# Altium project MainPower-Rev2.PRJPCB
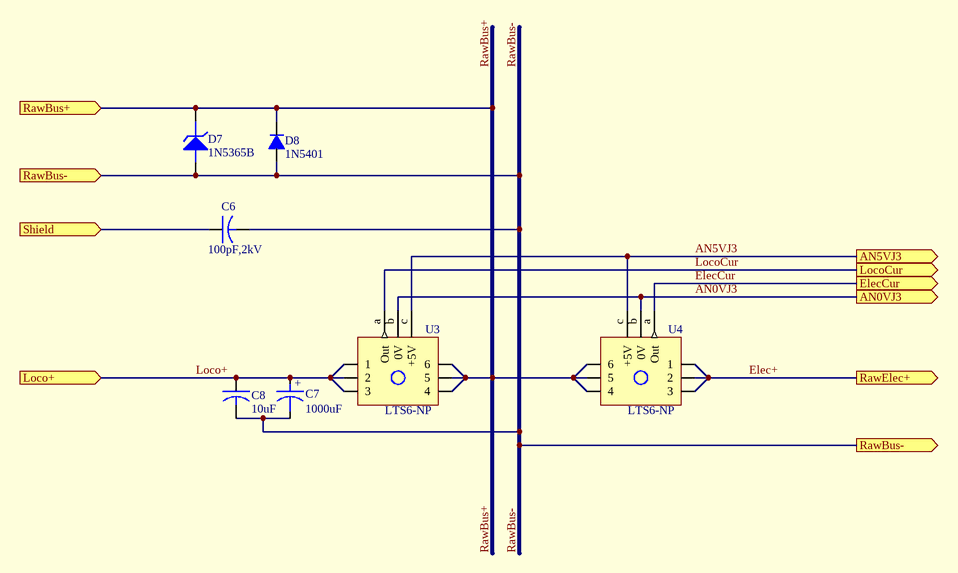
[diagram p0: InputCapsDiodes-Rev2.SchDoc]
8 sheets, 82 parts. Net scope: flat (ports and power ports of the same name join across sheets).
Board file: MainPower-Rev2.PcbDoc
Sheets:
  InputCapsDiodes-Rev2.SchDoc
  Iso5V-25W-MVC-Rev2.SchDoc
  Iso12V-30W-MVC-Rev2.SchDoc
  Iso9V-1W-Parosci-Rev2.SchDoc
  NonIso3.3V-5W-GPS-Rev2.SchDoc
  NonIso5V-13W-Iridium-Rev2.SchDoc
  BattBacked-Rev2.SCHDOC
  Watchdog-Rev2.SchDoc

## Sheet InputCapsDiodes-Rev2.SchDoc
size Tabloid; Organization: Monterey Bay Aquarium Research Institute; Address1: 7700 Sandholdt Rd; Address2: Moss Landing, CA 95039-9644; CompanyName: MBARI

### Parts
C6  100pF,2kV  [ECK]
C7  1000uF  [RAD0.3L_0.63D]
C8  10uF  [CAPSTICK-CS4-5]
D7  1N5365B  [DO-201AD]
D8  1N5401  [DO-201AD]
U3  LTS6-NP  [LTS6-NP]
U4  LTS6-NP  [LTS6-NP]

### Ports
AN0VJ3 (out), AN5VJ3 (out), ElecCur (out), Loco+ (in), LocoCur (out), RawBus+ (in), RawBus- (in), RawBus- (out), RawElec+ (out), Shield (in)

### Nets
AN0VJ3: U3.b(0V) U4.b(0V) ; port AN0VJ3
AN5VJ3: U3.c(+5V) U4.c(+5V) ; port AN5VJ3
Elec+: U4.1 U4.2 U4.3 ; port RawElec+
ElecCur: U4.a(Out) ; port ElecCur
Loco+: C7.1 C8.1 U3.1 U3.2 U3.3 ; port Loco+
LocoCur: U3.a(Out) ; port LocoCur
RawBus+: D7.2(K) D8.2(A) U3.4 U3.5 U3.6 U4.4 U4.5 U4.6 ; port RawBus+
RawBus-: C6.2 C7.2 C8.2 D7.1(A) D8.1(K) ; port RawBus-
NetC6_1: C6.1 ; port Shield

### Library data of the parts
C6 = CAPACITOR: ManufPartNo: ECK-T3D101KB; Manufacturer: Panasonic; VendorPartNo: PCC2092CT-ND; Cost/ea: 0.99; Reference: T033, 764; Vendor: Digi-Key
C7 = CAPACITOR POL: Capacitor; ManufPartNo: EEU-FC1H102; Manufacturer: Panasonic; VendorPartNo: P10333-ND; Cost/ea: 1.485; Vendor: Digi-Key
C8 = CAPACITOR: ManufPartNo: 106K050CS4G; Manufacturer: ITW Paktron; VendorPartNo: AMP50V106-K10G; Cost/ea: 8.04; Vendor: Future
D7 = ZENER3: Zener Diode; ManufPartNo: 2EZ36D5; Manufacturer: Microsemi; VendorPartNo: 2EZ36D5MSCT-ND; Cost/ea: 0.75; Vendor: Digi-Key
D8 = DIODE_S: Diode; ManufPartNo: 1N5401-T; Manufacturer: Diodes Inc; VendorPartNo: 1N5401DICT-ND; Cost/ea: 0.41; Reference: T033, 578; Vendor: Digi-Key
U3 U4 = LTS6-NP: Current Transducer; Manufacturer: LEM; VendorPartNo: 398-1000-ND; Vendor: Digi-Key; Cost/ea: 19.20

## Sheet Iso5V-25W-MVC-Rev2.SchDoc
size Tabloid; Organization: Monterey Bay Aquarium Research Institute; Address1: 7700 Sandholdt Rd; Address2: Moss Landing, CA 95039-9644; CompanyName: MBARI
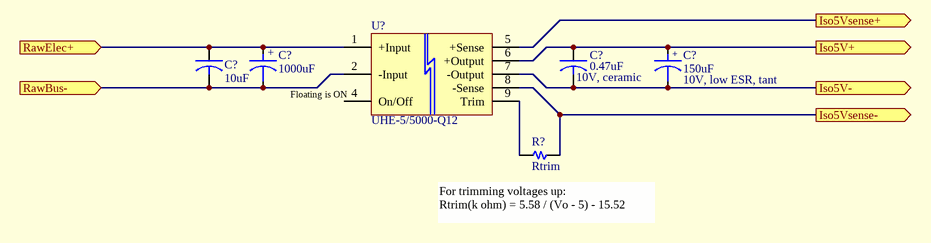
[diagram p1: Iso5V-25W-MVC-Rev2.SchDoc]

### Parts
C9  1000uF  [RAD0.3L_0.63D]
C10  10uF  [CAPSTICK-CS4-5]
C12  150uF  DescSheet: 10V, low ESR, tant  [7343pol]
C?  0.47uF  DescSheet: 10V, ceramic
R6  Rtrim  [AXIAL0.7]
U5  UHE-5/5000-Q12  [DATEL-UHE]

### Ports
Iso5V+ (out), Iso5V- (out), Iso5Vsense+ (out), Iso5Vsense- (out), RawBus- (in), RawElec+ (in)

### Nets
Elec+: C9.1 C10.1 U5.1(+Input) ; port RawElec+
RawBus-: C9.2 C10.2 U5.2(-Input) ; port RawBus-
NetC12_1: C12.1 C?.1 U5.6(+Output) ; port Iso5V+
NetC12_2: C12.2 C?.2 U5.7(-Output) ; port Iso5V-
NetR6_1: R6.1 U5.9(Trim)
NetR6_2: R6.2 U5.8(-Sense) ; port Iso5Vsense-
NetU5_5: U5.5(+Sense) ; port Iso5Vsense+

Not connected (* = marked no-connect by the designer): U5 4(On/Off)

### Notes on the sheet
- (near U5) Floating is ON
- (near R6) For trimming voltages up:
  Rtrim(k ohm) = 5.58 / (Vo - 5) - 15.52

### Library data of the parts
C9 = CAPACITOR POL: Capacitor
C10 C? = CAPACITOR
C12 = CAPACITOR POL: Tantalum Capacitor; ManufPartNo: EEJ-L1AD157R; Manufacturer: Panasonic; VendorPartNo: P11289CT-ND; Cost/ea: 1.884; Vendor: Digi-Key
R6 = RESISTOR
U5 = UHE: Datel UHE DC->DC Isolated Converter; Cost/ea: 61.90

## Sheet Iso12V-30W-MVC-Rev2.SchDoc
size Tabloid; Organization: Monterey Bay Aquarium Research Institute; Address1: 7700 Sandholdt Rd; Address2: Moss Landing, CA 95039-9644; CompanyName: MBARI
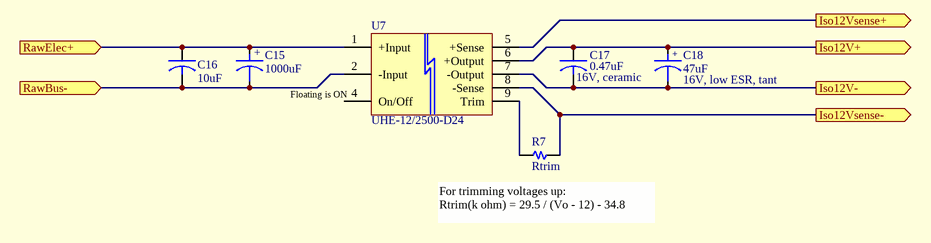
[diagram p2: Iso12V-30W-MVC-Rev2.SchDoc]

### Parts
C15  1000uF  [RAD0.3L_0.63D]
C16  10uF  [CAPSTICK-CS4-5]
C17  0.47uF  DescSheet: 16V, ceramic  [0805]
C18  47uF  DescSheet: 16V, low ESR, tant  [7343pol]
R7  Rtrim  [AXIAL0.7]
U7  UHE-12/2500-D24  [DATEL-UHE]

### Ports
Iso12V+ (out), Iso12V- (out), Iso12Vsense+ (out), Iso12Vsense- (out), RawBus- (in), RawElec+ (in)

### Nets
Elec+: C15.1 C16.1 U7.1(+Input) ; port RawElec+
RawBus-: C15.2 C16.2 U7.2(-Input) ; port RawBus-
NetC13_1: C17.1 C18.1 U7.6(+Output) ; port Iso12V+
NetC13_2: C17.2 C18.2 U7.7(-Output) ; port Iso12V-
NetR7_1: R7.1 U7.9(Trim)
NetR7_2: R7.2 U7.8(-Sense) ; port Iso12Vsense-
NetU7_5: U7.5(+Sense) ; port Iso12Vsense+

Not connected (* = marked no-connect by the designer): U7 4(On/Off)

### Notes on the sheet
- (near U7) Floating is ON
- (near R7) For trimming voltages up:
  Rtrim(k ohm) = 29.5 / (Vo - 12) - 34.8

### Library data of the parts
C15 = CAPACITOR POL: as C7 on sheet InputCapsDiodes-Rev2
C16 = CAPACITOR: as C8 on sheet InputCapsDiodes-Rev2
C17 = CAPACITOR: ManufPartNo: ECJ-2YB1C474K; Manufacturer: Panasonic; VendorPartNo: PCC1818CT-ND; Cost/ea: 0.245; Reference: T033, 771; Vendor: Digi-Key
C18 = CAPACITOR POL: Tantalum Capacitor; ManufPartNo: EEJ-L1CD476R; Manufacturer: Panasonic; VendorPartNo: P11291CT-ND; Cost/ea: 1.605; Vendor: Digi-Key
R7 = RESISTOR
U7 = UHE: Datel UHE DC->DC Isolated Converter; Cost/ea: 58.90

## Sheet Iso9V-1W-Parosci-Rev2.SchDoc
size Tabloid; Organization: Monterey Bay Aquarium Research Institute; Address1: 7700 Sandholdt Rd; Address2: Moss Landing, CA 95039-9644; CompanyName: MBARI
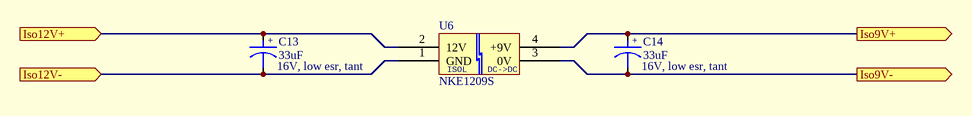
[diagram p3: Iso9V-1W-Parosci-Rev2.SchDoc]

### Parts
C13  33uF  DescSheet: 16V, low esr, tant  [6032pol]
C14  33uF  DescSheet: 16V, low esr, tant  [6032pol]
U6  NKE1209S  [NKEDCDC]

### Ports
Iso9V+ (out), Iso9V- (out), Iso12V+ (in), Iso12V- (in)

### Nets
NetC13_1: C13.1 U6.2(12V) ; port Iso12V+
NetC13_2: C13.2 U6.1(GND) ; port Iso12V-
NetC14_1: C14.1 U6.4(+9V) ; port Iso9V+
NetC14_2: C14.2 U6.3(0V) ; port Iso9V-

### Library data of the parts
C13 C14 = CAPACITOR POL: Capacitor; ManufPartNo: EEJ-L1CC336R; Manufacturer: Panasonic; VendorPartNo: P11290CT-ND; Cost/ea: 1.057; Vendor: Digi-Key
U6 = NKE1209S: DC->DC Isol Converter 12->9VDC; Manufacturer: C&D Technologies; VendorPartNo: 580-NKE1209S; Cost/ea: 8.33; Reference: Cat616, 1032; Vendor: Mouser

## Sheet NonIso3.3V-5W-GPS-Rev2.SchDoc
size Tabloid; Organization: Monterey Bay Aquarium Research Institute; Address1: 7700 Sandholdt Rd; Address2: Moss Landing, CA 95039-9644; CompanyName: MBARI
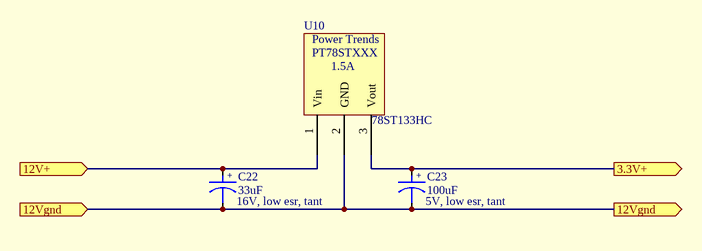
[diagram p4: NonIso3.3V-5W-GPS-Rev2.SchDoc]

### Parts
C22  33uF  DescSheet: 16V, low esr, tant  [6032pol]
C23  100uF  DescSheet: 5V, low esr, tant  [6032pol]
U10  78ST133HC  [PT78ST-HORIZ]

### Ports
3.3V+ (out), 12V+ (in), 12Vgnd (in), 12Vgnd (out)

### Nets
NetC22_1: C22.1 U10.1(Vin) ; port 12V+
NetC22_2: C22.2 C23.2 U10.2(GND) ; port 12Vgnd
NetC23_1: C23.1 U10.3(Vout) ; port 3.3V+

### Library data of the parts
C22 = CAPACITOR POL: Capacitor; ManufPartNo: EEJ-L1CC336R; Manufacturer: Panasonic; VendorPartNo: P11290CT-ND; Cost/ea: 1.057; Reference: T033, 718; Vendor: Digi-Key
C23 = CAPACITOR POL: Capacitor; ManufPartNo: EEJ-L0JC107R; Manufacturer: Panasonic; VendorPartNo: P11284CT-ND; Cost/ea: 1.196; Reference: T033, 718; Vendor: Digi-Key
U10 = PT78STXXX: Power Trends Switching Reg; Manufacturer: TI Power Trends; VendorPartNo: 78ST133HC-ND; Cost/ea: 15.38; Reference: T033, 1102; Vendor: Digi-Key

## Sheet NonIso5V-13W-Iridium-Rev2.SchDoc
size Tabloid; Organization: Monterey Bay Aquarium Research Institute; Address1: 7700 Sandholdt Rd; Address2: Moss Landing, CA 95039-9644; CompanyName: MBARI
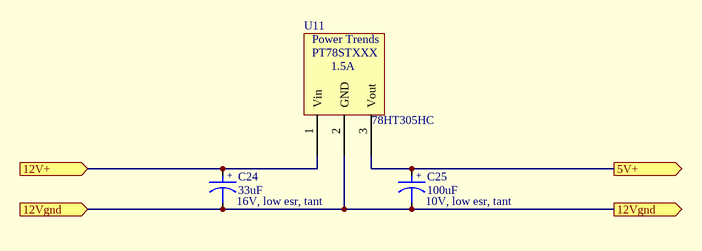
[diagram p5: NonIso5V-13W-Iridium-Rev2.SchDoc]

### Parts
C24  33uF  DescSheet: 16V, low esr, tant  [6032pol]
C25  100uF  DescSheet: 10V, low esr, tant  [7343pol]
U11  78HT305HC  [PT78ST-HORIZ]

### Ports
5V+ (out), 12V+ (in), 12Vgnd (in), 12Vgnd (out)

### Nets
NetC22_1: C24.1 U11.1(Vin) ; port 12V+
NetC22_2: C24.2 C25.2 U11.2(GND) ; port 12Vgnd
NetC25_1: C25.1 U11.3(Vout) ; port 5V+

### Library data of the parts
C24 = CAPACITOR POL: as C22 on sheet NonIso3.3V-5W-GPS-Rev2
C25 = CAPACITOR POL: Capacitor; ManufPartNo: EEJ-L1AD107R; Manufacturer: Panasonic; VendorPartNo: P11288CT-ND; Cost/ea: 1.688; Reference: T033, 718; Vendor: Digi-Key
U11 = PT78STXXX: Power Trends Switching Reg 5V, 3A; Manufacturer: TI Power Trends; VendorPartNo: 78HT305HC-ND; Cost/ea: 22.50; Reference: T033, 1103; Vendor: Digi-Key

## Sheet BattBacked-Rev2.SCHDOC
size Tabloid; Organization: Monterey Bay Aquarium Research Institute; Address1: 7700 Sandholdt Rd; Address2: Moss Landing, CA 95039-9644; CompanyName: MBARI
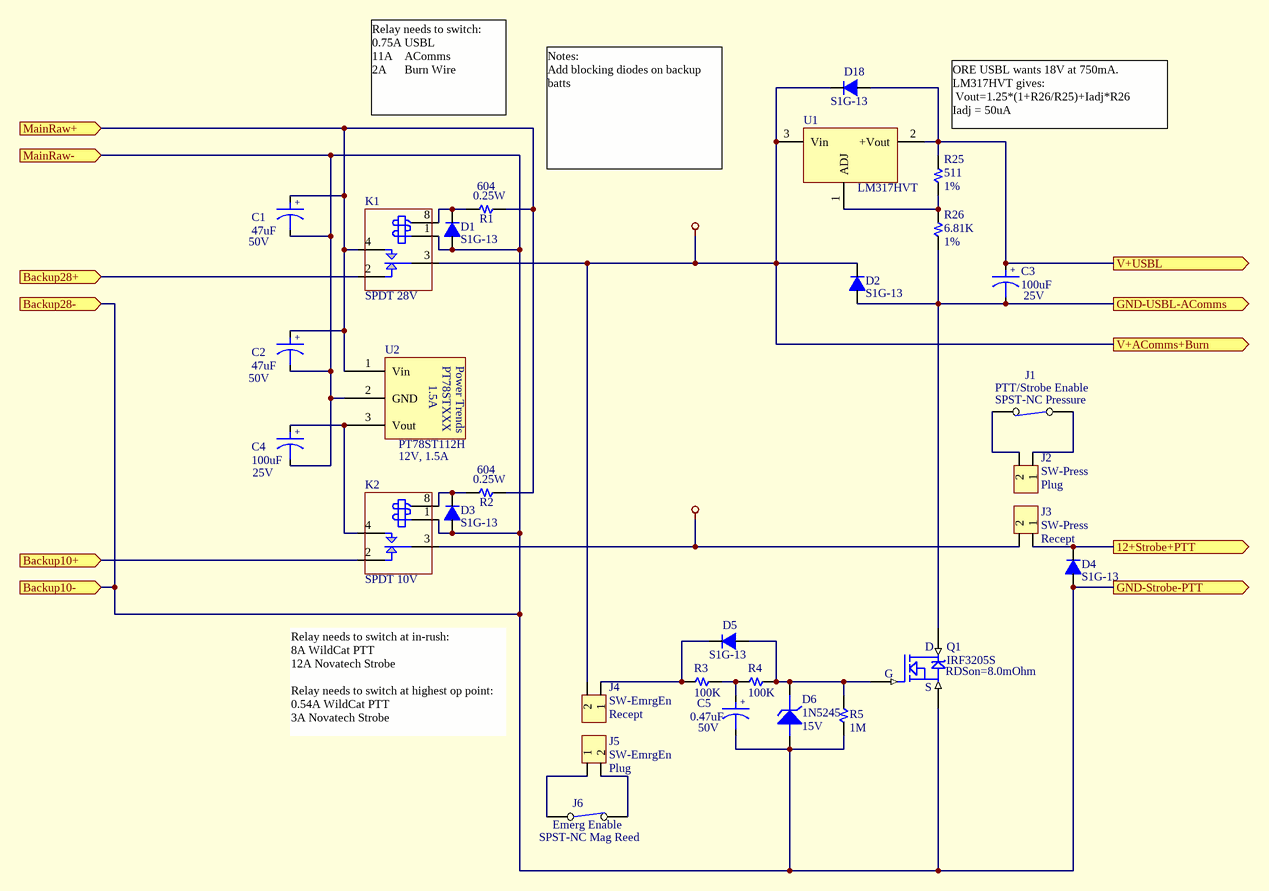
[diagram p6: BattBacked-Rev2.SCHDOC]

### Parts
C1  47uF  DescSheet: 50V  [RAD0.1L_0.25D]
C2  47uF  DescSheet: 50V  [RAD0.1L_0.25D]
C3  100uF  DescSheet: 25V  [RAD0.1L_0.25D]
C4  100uF  DescSheet: 25V  [RAD0.1L_0.25D]
C5  0.47uF  DescSheet: 50V  [RAD0.2_POL]
D1  S1G-13  [SMA]
D2  S1G-13  [SMA]
D3  S1G-13  [SMA]
D4  S1G-13  [SMA]
D5  S1G-13  [SMA]
D6  1N5245  DescSheet: 15V  [DIODE0.25]
D18  S1G-13  [SMA]
J1  PTT/Strobe Enable  DescSheet: SPST-NC Pressure  [CGRID2]  (mechanical)
J2  SW-Press  DescSheet: Plug  [CGRID2]  (mechanical)
J3  SW-Press  DescSheet: Recept  [CGRID2]
J4  SW-EmrgEn  DescSheet: Recept  [CGRID2]
J5  SW-EmrgEn  DescSheet: Plug  [CGRID2]  (mechanical)
J6  Emerg Enable  DescSheet: SPST-NC Mag Reed  [CGRID2]  (mechanical)
K1  SPDT 28V  [NAIS-LZ]
K2  SPDT 10V  [NAIS-LZ]
Q1  IRF3205S  DescSheet: RDSon=8.0mOhm  [D2PAK]
R1  604  DescSheet: 0.25W  [AXIAL0.7]
R2  604  DescSheet: 0.25W  [AXIAL0.7]
R3  100K  [0805]
R4  100K  [0805]
R5  1M  [0805]
R25  511  DescSheet: 1%  [0805]
R26  6.81K  DescSheet: 1%  [0805]
U1  LM317HVT  [TO-220]
U2  PT78ST112H  DescSheet: 12V, 1.5A  [PT78ST-HORIZ]

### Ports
12+Strobe+PTT (out), Backup10+ (in), Backup10- (in), Backup28+ (in), Backup28- (in), GND-Strobe-PTT (out), GND-USBL-AComms (out), MainRaw+ (in), MainRaw- (in), V+AComms+Burn (out), V+USBL (out)

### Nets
SW10VDC: J3.2 K2.3(COMMON)
SW28VDC: D2.2(A) D18.2(A) J4.2 K1.3(COMMON) U1.3(Vin) ; port V+AComms+Burn
NetC1_1: C1.1 C2.1 K1.4(NO) R1.2 R2.2 U2.1(Vin) ; port MainRaw+
NetC1_2: C1.2 C2.2 C4.2 C5.2 D1.1(K) D3.1(K) D4.1(K) D6.1(A) K1.1(COIL+) K2.1(COIL+) Q1.3(S) R5.1 U2.2(GND) ; port Backup28-, port MainRaw-, port Backup10-, port GND-Strobe-PTT
NetC3_1: C3.1 D18.1(K) R25.1 U1.2(+Vout) ; port V+USBL
NetC3_2: C3.2 D2.1(K) Q1.2(D) R26.1 ; port GND-USBL-AComms
NetC4_1: C4.1 K2.4(NO) U2.3(Vout)
NetC5_1: C5.1 R3.2 R4.1
NetD1_2: D1.2(A) K1.8(COIL-) R1.1
NetD3_2: D3.2(A) K2.8(COIL-) R2.1
NetD4_2: D4.2(A) J3.1 ; port 12+Strobe+PTT
NetD5_1: D5.1(K) D6.2(K) Q1.1(G) R4.2 R5.2
NetD5_2: D5.2(A) J4.1 R3.1
NetJ1_1: J1.1(COMMON) J2.1
NetJ1_2: J1.2(NO) J2.2
NetJ5_1: J5.1 J6.1(COMMON)
NetJ5_2: J5.2 J6.2(NO)
NetK1_2: K1.2(NC) ; port Backup28+
NetK2_2: K2.2(NC) ; port Backup10+
NetR25_2: R25.2 R26.2 U1.1(ADJ)

Not connected (* = marked no-connect by the designer): K1 5(NO) 6(COMMON) 7(NC); K2 5(NO) 6(COMMON) 7(NC)

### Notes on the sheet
- Relay needs to switch:
  0.75A USBL
  11A    AComms
  2A      Burn Wire
- ORE USBL wants 18V at 750mA.
  LM317HVT gives:
  Vout=1.25*(1+R26/R25)+Iadj*R26
  Iadj = 50uA
- Notes:
  Add blocking diodes on backup batts
- Relay needs to switch at in-rush:
  8A WildCat PTT
  12A Novatech Strobe
  Relay needs to switch at highest op point:
  0.54A WildCat PTT
  3A Novatech Strobe

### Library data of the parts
C1 C2 = CAPACITOR POL: Capacitor; ManufPartNo: EEU-FC1H470; Manufacturer: Panasonic; VendorPartNo: P10321-ND; Cost/ea: 0.23; Reference: T033, 695; Vendor: Digi-Key
C3 C4 = CAPACITOR POL: Capacitor; ManufPartNo: EEU-FC1E101S; Manufacturer: Panasonic; VendorPartNo: P10269-ND; Cost/ea: 0.23; Reference: T033, 694; Vendor: Digi-Key
C5 = CAPACITOR POL: Capacitor; ManufPartNo: 222237012474; Manufacturer: BC Components; VendorPartNo: 3017PH-ND; Cost/ea: 0.348; Reference: T033, 736; Vendor: Digi-Key
D1-D5 D18 = DIODE_S: Diode; Manufacturer: Diodes Inc; VendorPartNo: S1GDICT-ND; Cost/ea: 0.288; DescSheet: 1A, 400V; Reference: T033, 578; Vendor: Digi-Key
D6 = ZENER3: Zener Diode; ManufPartNo: 1N5245B; Manufacturer: Diodes Inc; VendorPartNo: 1N5245BDICT-ND; Cost/ea: 0.21; Reference: T033, 564; Vendor: Digi-Key
J1 J6 = SW-SPST-NC: Manufacturer: Molex; VendorPartNo: WM2900-ND; Cost/ea: 0.38; Reference: T033, 94; Vendor: Digi-Key
J2 J5 = CON2: Connector; Manufacturer: Molex; VendorPartNo: WM2900-ND; Cost/ea: 0.38; Reference: T033, 94; Vendor: Digi-Key
J3 J4 = CON2: Connector; ManufPartNo: 70543-0001; Manufacturer: Molex; VendorPartNo: WM4800-ND; Cost/ea: 0.711; Reference: T033, 94; Vendor: Digi-Key
K1 K2 = RELAY-NAIS-LZ-SPDT: Nais LZ Relay SPDT; ManufPartNo: ALZ12F24; VendorPartNo: 255-1447-ND; Cost/ea: 2.16; Reference: T033, 942; Vendor: Digi-Key
Q1 = HEXFET-N: HexFET; Manufacturer: International Rectifier; VendorPartNo: IRF3205S-ND; Cost/ea: 2.72; Reference: T033, 549; Vendor: Digi-Key
R1 R2 = RESISTOR: ManufPartNo: MFR-25FBF-604R; Manufacturer: Yaego; VendorPartNo: 604XBK-ND; Cost/ea: 0.108; Reference: T033, 807; Vendor: Digi-Key
R3 R4 = RESISTOR: ManufPartNo: ERJ-6ENF1003V; Manufacturer: Panasonic; VendorPartNo: P100KCCT-ND; Cost/ea: 0.091; Reference: T033, 801; Vendor: Digi-Key
R5 = RESISTOR: ManufPartNo: ERJ-6ENF1004V; Manufacturer: Panasonic; VendorPartNo: P1.00MCCT-ND; Cost/ea: 0.091; Reference: T033, 801; Vendor: Digi-Key
R25 = RESISTOR: ManufPartNo: ERJ-6ENF5110V; Manufacturer: Panasonic; VendorPartNo: P511CCT-ND; Cost/ea: 0.091; Reference: T033, 801; Vendor: Digi-Key
R26 = RESISTOR: ManufPartNo: ERJ-6ENF6811V; Manufacturer: Panasonic; VendorPartNo: P6.81KCCT-ND; Cost/ea: 0.091; Reference: T033, 801; Vendor: Digi-Key
U1 = LM317HVT: Regulator; Manufacturer: National Semi; VendorPartNo: LM317HVT-ND; Cost/ea: 2.79; Reference: T033, 446; Vendor: Digi-Key
U2 = PT78STXXX: Power Trends Switching Reg; Manufacturer: TI PowerTrends; VendorPartNo: PT78ST112H-ND; Cost/ea: 14.46; Reference: T033, 1104; Vendor: Digi-Key

## Sheet Watchdog-Rev2.SchDoc
size Tabloid; Organization: Monterey Bay Aquarium Research Institute; Address1: 7700 Sandholdt Rd; Address2: Moss Landing, CA 95039-9644; CompanyName: MBARI
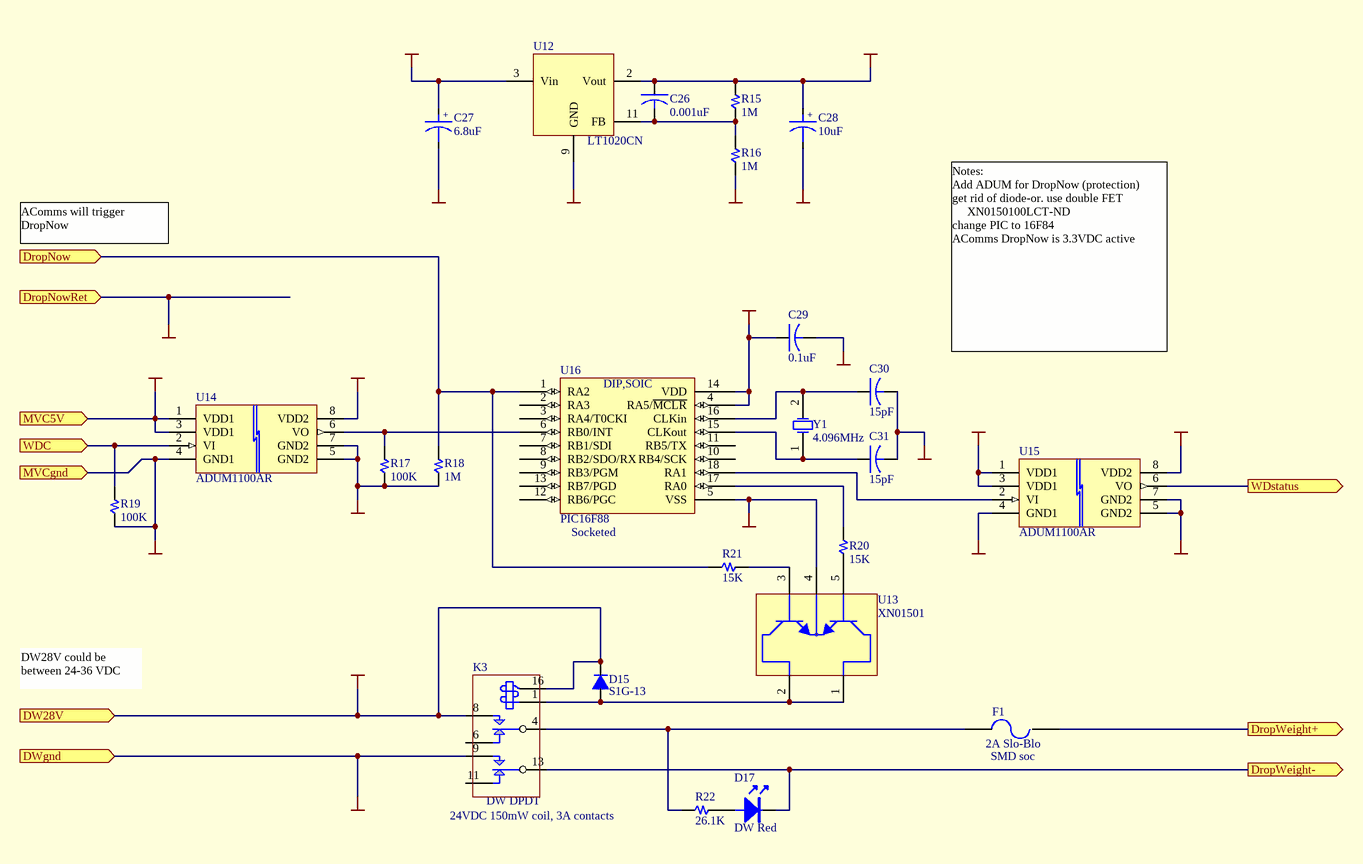
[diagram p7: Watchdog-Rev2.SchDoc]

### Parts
C26  0.001uF  [0805]
C27  6.8uF  [7343pol]
C28  10uF  [6032pol]
C29  0.1uF  [0805]
C30  15pF  [0805]
C31  15pF  [0805]
D15  S1G-13  [SMA]
D17  DW Red  [SOT-23]
F1  2A Slo-Blo  DescSheet: SMD soc  [SMF-OMNIBLOK]
K3  DW DPDT  DescSheet: 24VDC 150mW coil, 3A contacts  [DIP16]
R15  1M  [0805]
R16  1M  [0805]
R17  100K  [0805]
R18  1M  [0805]
R19  100K  [0805]
R20  15K  [0805]
R21  15K  [0805]
R22  26.1K  [0805]
U12  LT1020CN  [DIP14]
U13  XN01501  [SC-74A]
U14  ADUM1100AR  [SO-G8/D5]
U15  ADUM1100AR  [SO-G8/D5]
U16  PIC16F88  DescSheet: Socketed  [DIP18]
Y1  4.096MHz  [MA-506]

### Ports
DropNow (in), DropNowRet (in), DropWeight+ (out), DropWeight- (out), DW28V (in), DWgnd (in), MVC5V (in), MVCgnd (in), WDC (in), WDstatus (out)

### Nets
DW5V: C26.1 C28.1 C29.1 R15.1 U12.2(Vout) U14.8(VDD2) U15.1(VDD1) U15.3(VDD1) U16.4(RA5/~{MCLR}) U16.14(VDD)
DW28V: C27.1 D15.2(A) K3.8(NO1) K3.16(COIL) U12.3(Vin) ; port DW28V
DWgnd: C27.2 C28.2 C29.2 C30.2 C31.2 K3.9(NO2) R16.2 R17.2 R18.2 U12.9(GND) U13.4(Emitter) U14.5(GND2) U14.7(GND2) U15.4(GND1) U16.5(VSS) ; port DWgnd, port DropNowRet
MVC5V: U14.1(VDD1) U14.3(VDD1) U15.8(VDD2) ; port MVC5V
MVCgnd: R19.2 U14.4(GND1) U15.5(GND2) U15.7(GND2) ; port MVCgnd
NetC26_2: C26.2 R15.2 R16.1 U12.11(FB)
NetC30_1: C30.1 U16.16(CLKin) Y1.2(OSC2)
NetC31_1: C31.1 U16.15(CLKout) Y1.1(OSC1)
NetD15_1: D15.1(K) K3.1(COIL) U13.1(C1) U13.2(C2)
NetD17_2: D17.2(A) R22.1
NetD17_3: D17.3(K) K3.13(COMMON2) ; port DropWeight-
NetF1_1: F1.1 K3.4(COMMON1) R22.2
NetF1_2: F1.2 ; port DropWeight+
NetR17_1: R17.1 U14.6(VO) U16.6(RB0/INT)
NetR18_1: R18.1 R21.2 U16.1(RA2) ; port DropNow
NetR19_1: R19.1 U14.2(VI) ; port WDC
NetR20_1: R20.1 U13.5(B1)
NetR20_2: R20.2 U16.17(RA0)
NetR21_1: R21.1 U13.3(B2)
NetU15_2: U15.2(VI) U16.18(RA1)
NetU15_6: U15.6(VO) ; port WDstatus

Not connected (* = marked no-connect by the designer): K3 6(NC1) 11(NC2); U16 2(RA3) 3(RA4/T0CKI) 7(RB1/SDI) 8(RB2/SDO/RX) 9(RB3/PGM) 10(RB4/SCK) 11(RB5/TX) 12(RB6/PGC) 13(RB7/PGD)

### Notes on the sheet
- AComms will trigger DropNow
- Notes:
  Add ADUM for DropNow (protection)
  get rid of diode-or. use double FET
  XN0150100LCT-ND
  change PIC to 16F84
  AComms DropNow is 3.3VDC active
- DW28V could be between 24-36 VDC

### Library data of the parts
C26 = CAPACITOR: ManufPartNo: ECJ-2VB1H102K; Manufacturer: Panasonic; VendorPartNo: PCC102BNCT-ND; Cost/ea: 0.062; DescSheet: 10V; Reference: T033, 771; Vendor: Digi-Key
C27 = CAPACITOR POL: Capacitor; ManufPartNo: T491D685M050AS; Manufacturer: Panasonic; VendorPartNo: 399-3109-1-ND; Cost/ea: 0.79; DescSheet: 50V; Reference: T033, 727; Vendor: Digi-Key
C28 = CAPACITOR POL: Capacitor; ManufPartNo: T491C106K010AS; Manufacturer: Panasonic; VendorPartNo: 399-1571-1-ND; Cost/ea: 0.32; DescSheet: 10V; Reference: T033, 726; Vendor: Digi-Key
C29 = CAPACITOR: ManufPartNo: ECJ-2YB1H104K; Manufacturer: Panasonic; VendorPartNo: PCC1840CT-ND; Cost/ea: 0.161; Reference: T033, 771; Vendor: Digi-Key
C30 C31 = CAPACITOR: ManufPartNo: ECJ-2VC1H150J; Manufacturer: Panasonic; VendorPartNo: PCC150CNCT-ND; Cost/ea: 0.062; Reference: T033, 770; Vendor: Digi-Key
D15 = DIODE_S: as D1 on sheet BattBacked-Rev2
D17 = LED: ManufPartNo: SML-LX15SRC-TR; Manufacturer: Lumex; VendorPartNo: 67-1660-1-ND; Cost/ea: 0.494; Reference: T033, 1194; Vendor: Digi-Key
F1 = Fuse 2: Fuse; Manufacturer: Littelfuse; ManufPartNo: 0154002.DRT; VendorPartNo: F1305CT-ND; Cost/ea: 2.63; Reference: T033, 1066; Vendor: Digi-Key
K3 = RELAY-PB-V23105: P&B V23105 Relay DPDT; ManufPartNo: V23105A5005A201; VendorPartNo: PB385-ND; Cost/ea: 1.78; Reference: T033, 946; Vendor: Digi-Key
R15 R16 R18 = RESISTOR: as R5 on sheet BattBacked-Rev2
R17 R19 = RESISTOR: as R3 on sheet BattBacked-Rev2
R20 R21 = RESISTOR: ManufPartNo: ERJ-6ENF1502V; Manufacturer: Panasonic; VendorPartNo: P15.0KCCT-ND; Cost/ea: 0.091; Reference: T033, 801; Vendor: Digi-Key
R22 = RESISTOR: ManufPartNo: ERJ-6ENF2612V; Manufacturer: Panasonic; VendorPartNo: P26.1KCCT-ND; Cost/ea: 0.091; DescSheet: 1/10W; Reference: T033, 801; Vendor: Digi-Key
U12 = LT1020: Micropower Regulator; Manufacturer: Linear Technology; VendorPartNo: LT1020CN-ND; Cost/ea: 6.88; Reference: T033, 463; Vendor: Digi-Key
U13 = XN01501: Dual NPN Common Emitter Transistor; ManufPartNo: XN0150100L; Manufacturer: Panasonic; VendorPartNo: XN0150100LCT-ND; Cost/ea: 0.41; Reference: T033, 529; Vendor: Digi-Key
U14 U15 = ADUM1100AR: Digital Isolator; Manufacturer: Analog Devices; Cost/ea: 4.19; Vendor: Arrow Electronics
U16 = PIC16F88: PIC16F88 microcontroller DIP,SOIC package; ManufPartNo: PIC16F88-I/P; Manufacturer: Microchip; VendorPartNo: PIC16F88-I/P-ND; Cost/ea: 4.58; Reference: T033, 303; Vendor: Digi-Key
Y1 = XTAL: Crystal Oscillator; pin to pad: 2>4; Manufacturer: Epson Elec; ManufPartNo: MA-506 4.0960M-C0; VendorPartNo: SE2619CT-ND; Cost/ea: 2.80; Reference: T033, 611; Vendor: Digi-Key

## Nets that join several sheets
Elec+: InputCapsDiodes-Rev2 (U4.1 U4.2 U4.3), Iso5V-25W-MVC-Rev2 (C9.1 C10.1 U5.1), Iso12V-30W-MVC-Rev2 (C15.1 C16.1 U7.1)
NetC13_1: Iso12V-30W-MVC-Rev2 (C17.1 C18.1 U7.6), Iso9V-1W-Parosci-Rev2 (C13.1 U6.2)
NetC13_2: Iso12V-30W-MVC-Rev2 (C17.2 C18.2 U7.7), Iso9V-1W-Parosci-Rev2 (C13.2 U6.1)
NetC22_1: NonIso3.3V-5W-GPS-Rev2 (C22.1 U10.1), NonIso5V-13W-Iridium-Rev2 (C24.1 U11.1)
NetC22_2: NonIso3.3V-5W-GPS-Rev2 (C22.2 C23.2 U10.2), NonIso5V-13W-Iridium-Rev2 (C24.2 C25.2 U11.2)
RawBus-: InputCapsDiodes-Rev2 (5 pins), Iso5V-25W-MVC-Rev2 (C9.2 C10.2 U5.2), Iso12V-30W-MVC-Rev2 (C15.2 C16.2 U7.2)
